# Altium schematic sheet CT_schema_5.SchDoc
size 302 x 256 mm
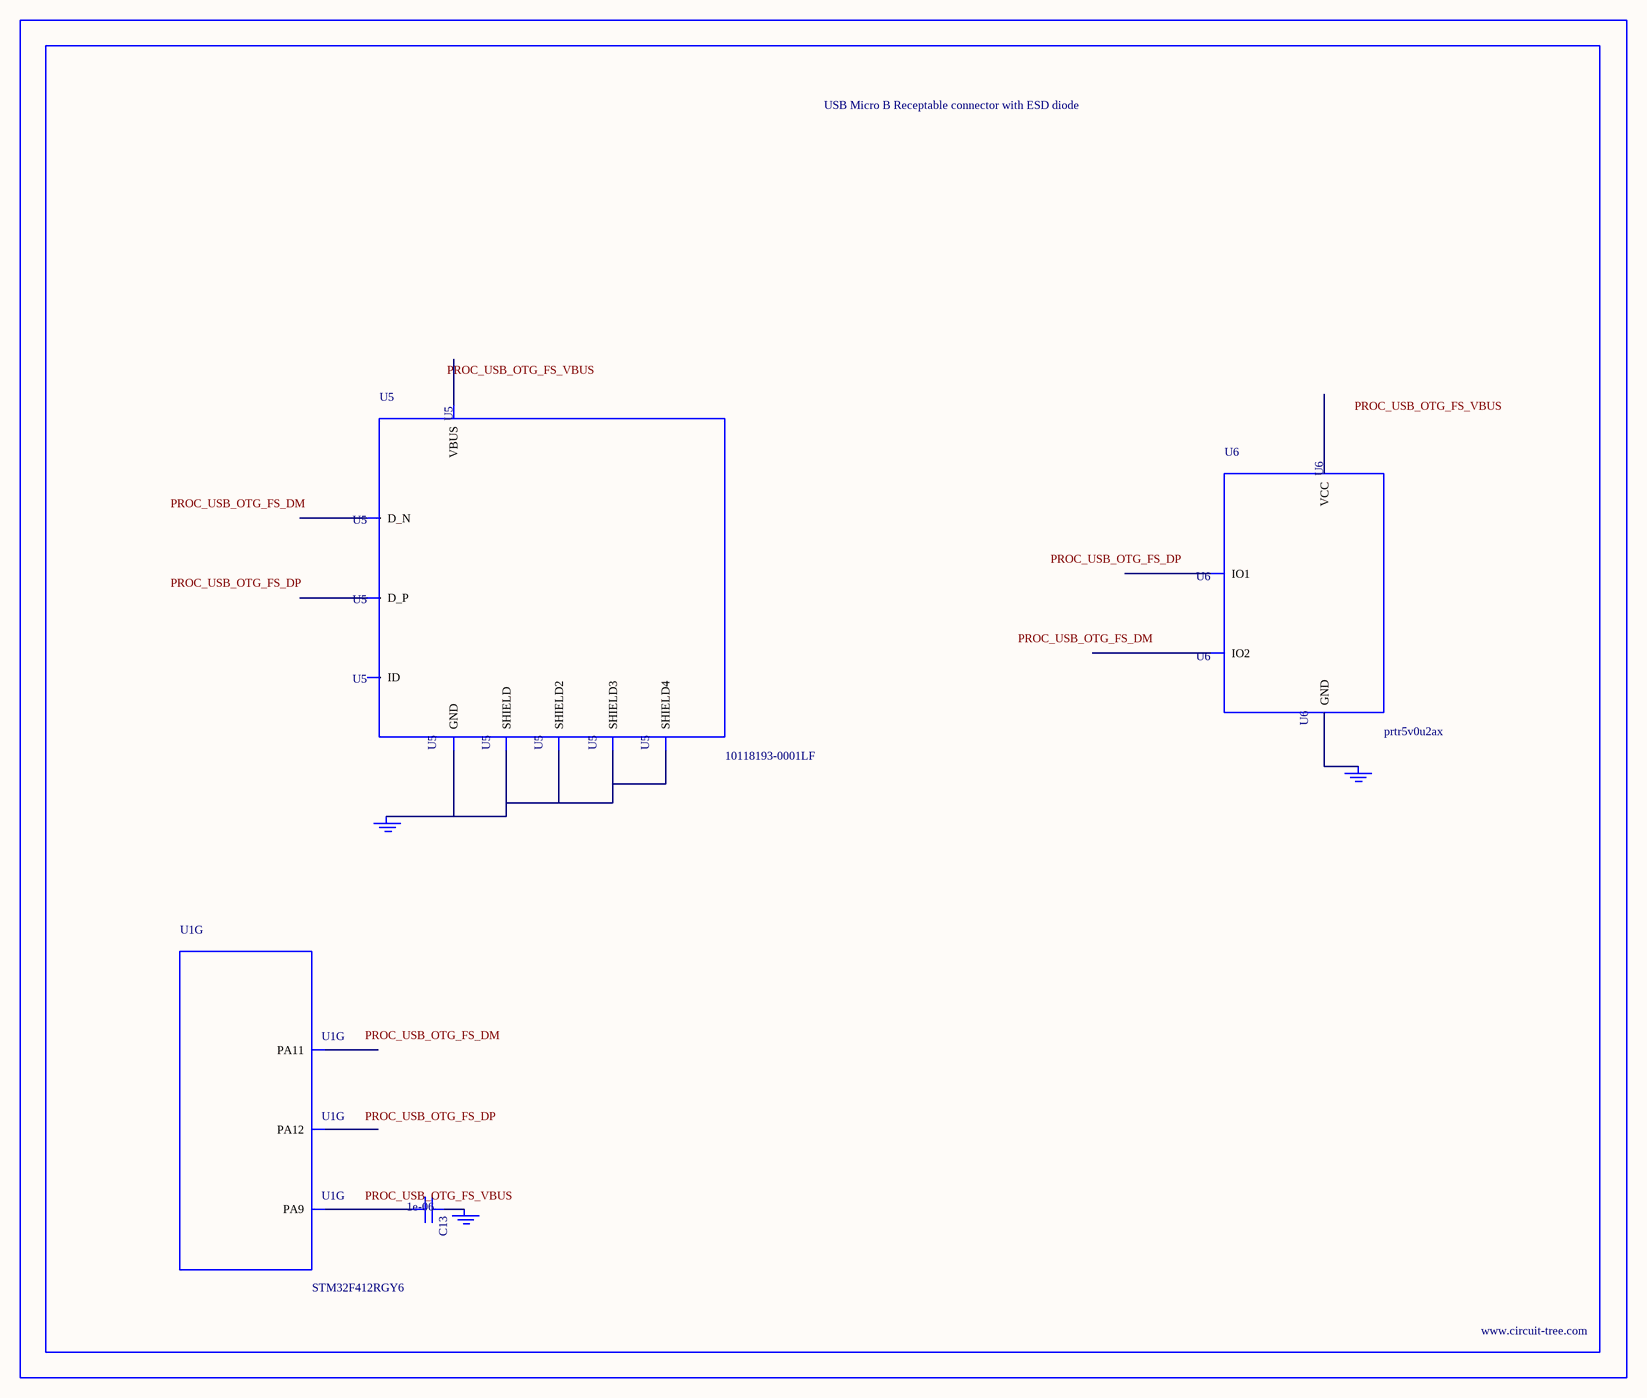
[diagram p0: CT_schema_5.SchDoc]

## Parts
BORDER4  (no value)
C13  1e-06  [C0603]
GND_INSTANCE_4_0  (no value)
GND_INSTANCE_4_1  (no value)
GND_INSTANCE_4_2  (no value)
U1  STM32F412RGY6  [WLCSP64]  (part G of 7)
U5  10118193-0001LF  [FCI_10118193-0001LF]
U6  prtr5v0u2ax  [SOT143B]

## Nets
NetC13_1: C13.1 GND_INSTANCE_4_1.0(GND)
NetC13_2: C13.2 U1.D1(PA9)
NetGND_INSTANCE_4_0_0: GND_INSTANCE_4_0.0(GND) U5.5(GND) U5.6(SHIELD) U5.7(SHIELD2) U5.8(SHIELD3) U5.9(SHIELD4)
NetGND_INSTANCE_4_2_0: GND_INSTANCE_4_2.0(GND) U6.1(GND)

Not connected (* = marked no-connect by the designer): U1 C1(PA12) D3(PA11); U5 1(VBUS) 2(D_N) 3(D_P) 4(ID); U6 2(IO1) 3(IO2) 4(VCC)

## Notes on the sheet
- Labels drawn without touching a wire or pin: PROC_USB_OTG_FS_DM, PROC_USB_OTG_FS_DP, PROC_USB_OTG_FS_VBUS

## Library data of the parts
BORDER4 = BORDER_PAGE4
C13 = C0603C105K3RACTU
GND_INSTANCE_4_0-GND_INSTANCE_4_2 = GND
